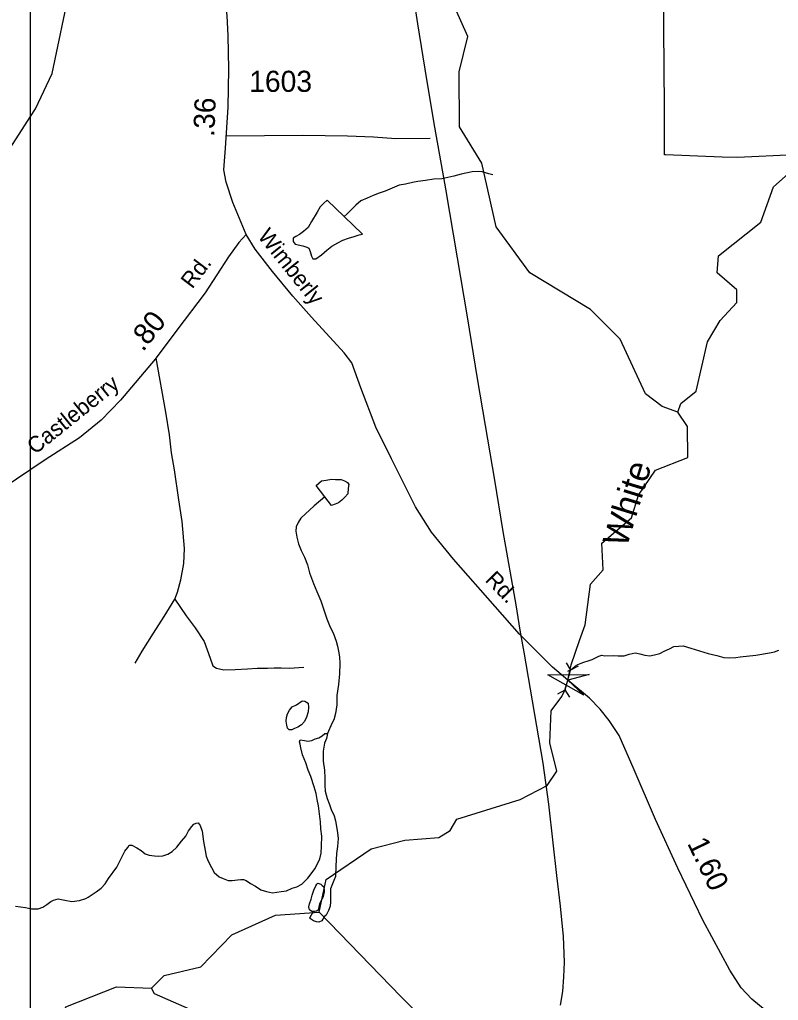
# Model space of a CAD drawing. Extents: x 2001466 to 2224147, y 644118 to 847247.
# Drawn here: x 2020409 to 2024898, y 729712 to 735517 of the extents above; entities that cross this region are included whole.
import ezdxf

# ---------------------------------------------------------------- set-up
doc = ezdxf.new("R2010")
doc.units = 0
for name, color, linetype in [('Exist Boundary Political City Limit New Hole', 7, 'Continuous'), ('Exist Hydrographic Creek Single Shore', 7, 'Continuous'), ('Exist Hydrographic Creek Single Shore Label', 7, 'Continuous'), ('Exist Hydrographic Misc Water Feature', 7, 'Continuous'), ('Exist Railroad Mainline', 7, 'Continuous'), ('Exist Road Non-System Type 51', 7, 'Continuous'), ('Exist Road Non-System Type 51 Label', 7, 'Continuous'), ('Exist Road Secondary Mileage Hundredths English Label', 7, 'Continuous'), ('Exist Road Secondary Structure Culvert CELL', 7, 'Continuous'), ('Exist Road Secondary Structure Standard Bridge Attributed CELL', 7, 'Continuous'), ('Exist Road Secondary Type 51 Attributed', 7, 'Continuous'), ('Exist Road Secondary Type 51 Label', 7, 'Continuous'), ('Exist Road Secondary Type 51 Number Label', 7, 'Continuous'), ('Map Preparation Boundary City Limit Buffer Line', 7, 'Continuous'), ('Map Preparation Inset Cut Line', 7, 'Continuous')]:
    doc.layers.add(name, color=color, linetype=linetype)

msp = doc.modelspace()

# ---------------------------------------------------------------- linework, layer by layer
at = {"layer": 'Exist Boundary Political City Limit New Hole'}
msp.add_lwpolyline([(2024992.9, 734716.5), (2024656.5, 734700.5), (2024565.2, 734702.9), (2024229.8, 734715.9), (2024225.1, 734716.1), (2024225.2, 735000), (2024214.4, 736161.1), (2024206.5, 737131.8), (2024409.8, 737216.6), (2024630.1, 737307.3), (2024732.8, 737349.6), (2024953, 736766.3)], dxfattribs=at)
at = {"layer": 'Exist Hydrographic Creek Single Shore'}
for points in [[(2024303.3, 733192.6), (2024320.3, 733244.8), (2024411.3, 733318.3), (2024478.4, 733609), (2024553.2, 733735.5), (2024653.3, 733841.7), (2024652.3, 733917.2), (2024536.4, 734018), (2024544.4, 734119.5), (2024794.4, 734317.9), (2024869.4, 734526.3), (2025377.3, 734978.6)], [(2023371.3, 730901.7), (2023530.4, 730983.8), (2023588.3, 731067.9), (2023546.4, 731236.1), (2023554.4, 731426.3), (2023616.1, 731511.5), (2023635.1, 731547.4), (2023652.7, 731608), (2023672.5, 731697.8), (2023721.3, 731842.8), (2023754.4, 731934), (2023787.4, 732176.1), (2023862.4, 732259.9), (2023854.4, 732417.6), (2024029.3, 732568.3), (2024070.3, 732701.9), (2024170.4, 732850.9), (2024362.3, 732925.7), (2024361.3, 733109.4), (2024303.3, 733192.6)], [(2022180.4, 730233.7), (2022222.4, 730426.5), (2022488.4, 730608), (2022688.3, 730659.8), (2022888.4, 730675.4), (2022955.3, 730716.6), (2022996.3, 730784.7), (2023371.3, 730901.7)], [(2021189.4, 729784.8), (2021264.4, 729858.7), (2021480.3, 729910.1), (2021664.5, 730099.9), (2021922.4, 730216), (2022180.4, 730233.7)], [(2020472.9, 729511.2), (2020531.4, 729473.4), (2020614.4, 729517.5), (2020681.4, 729673.7), (2020981.4, 729792.3), (2021189.4, 729784.8)]]:
    msp.add_lwpolyline(points, dxfattribs=at)
at = {"layer": 'Exist Hydrographic Misc Water Feature'}
for p, q in [((2022145.9, 730237.7), (2022124.2, 730198)), ((2022664.3, 729734.9), (2022180.4, 730233.7))]:
    msp.add_line(p, q, dxfattribs=at)
for points in [[(2024303.3, 733192.6), (2024211.4, 733227.3), (2024111.4, 733301.5), (2023961.3, 733626.2), (2023786.3, 733800.4), (2023428.3, 734017.7), (2023228.4, 734290.8), (2023144.3, 734666.5), (2023011.3, 734882.5), (2023010.4, 735207.3), (2023060.3, 735416.3), (2022985.4, 735585.2), (2023035.2, 735843.4), (2023060.3, 736390.8), (2023134.3, 736642), (2023109.3, 736701.5), (2022826.3, 736891.1), (2022626.4, 737118.3), (2022301.4, 737308.6), (2022042.4, 737707.6)], [(2020472.9, 734943.6), (2020502.4, 734989.5), (2020602.3, 735197.4), (2020710.4, 735716.9), (2020719.4, 735874.2), (2021060.4, 736307), (2021102.4, 736407.8), (2021368.4, 736556.6), (2021426.7, 736674)], [(2019229.5, 733365.1), (2019578.5, 733699.2), (2019703.3, 733765.6), (2019837.5, 733907.1), (2019887.3, 734040.7), (2020070.4, 734224), (2020178.5, 734280.8), (2020344.3, 734582.5), (2020352.3, 734756.3), (2020472.9, 734943.6)], [(2023207.7, 734598.8), (2023185.8, 734605), (2023165.7, 734610.3), (2023145.6, 734616.5), (2023121.6, 734618.6), (2023085.7, 734616.8), (2023021.5, 734602.6), (2022977.6, 734590.3), (2022941.7, 734582.1), (2022907.9, 734574.5), (2022859.7, 734572.3), (2022809.7, 734564.3), (2022765.8, 734558.6), (2022733.6, 734551.8), (2022691.6, 734543.7), (2022653.6, 734536.2), (2022571.8, 734501.8), (2022535.9, 734490.3), (2022500.1, 734475.4), (2022466, 734459.7), (2022427.9, 734444.1), (2022397.9, 734419.3), (2022368.2, 734389.5), (2022346.3, 734367.8), (2022329.5, 734350.9)], [(2022329.5, 734350.9), (2022228.2, 734447.3), (2022208.1, 734429.7), (2022186.1, 734409.6), (2022168.3, 734377.2), (2022136.3, 734321.2), (2022116.4, 734287.2), (2022088.1, 734263.1), (2022064.3, 734244.8), (2022042.4, 734233), (2022028.2, 734223.4), (2022026.4, 734202.9), (2022038.3, 734187.1), (2022084.4, 734178.8), (2022108.6, 734169.2), (2022120.3, 734164.9), (2022128.5, 734143.4), (2022136.5, 734117), (2022144.5, 734101.3), (2022160.5, 734100.9), (2022194.3, 734125.6), (2022226.5, 734151.3), (2022256.2, 734175.2), (2022292.5, 734195.8), (2022320.4, 734211.6), (2022354.3, 734223.3), (2022388.1, 734233.3), (2022418.2, 734243.3), (2022438.1, 734247.8), (2022329.5, 734350.9)], [(2022214.4, 732692.2), (2022162.5, 732758.9), (2022194.5, 732786.9), (2022222.4, 732790.4), (2022254.4, 732797.2), (2022278.4, 732795.1), (2022310.4, 732795.2), (2022330.5, 732786.6), (2022348.5, 732777.3), (2022356.5, 732764.7), (2022352.6, 732742.7), (2022350.8, 732709.1), (2022332.5, 732690.6), (2022314.7, 732672.9), (2022294.6, 732656.9), (2022274.9, 732649.1), (2022254.8, 732640.5), (2022214.4, 732692.2)], [(2022214.4, 732692.2), (2022151.1, 732638.6), (2022072.7, 732566.3), (2022057.1, 732540.4), (2022045, 732514.4), (2022043.2, 732488.2), (2022049.1, 732454.4), (2022059.2, 732414.8), (2022075.2, 732374.3), (2022093.4, 732336.2), (2022111.5, 732290.8), (2022123.4, 732242.1), (2022147.6, 732178.4), (2022167.7, 732132.1), (2022191.7, 732076.6), (2022211.8, 732012.3), (2022225.9, 731970.2), (2022245.8, 731920.5), (2022264, 731886.5), (2022281.9, 731838.6), (2022290.1, 731808.9), (2022296.2, 731778.4), (2022302.2, 731746.3), (2022304, 731706.1), (2022302.4, 731644.6), (2022296.4, 731582.3), (2022286.6, 731516.1), (2022286.6, 731460.4), (2022278.6, 731410.5), (2022268.8, 731372.1), (2022256.7, 731350.2), (2022230.2, 731291.7)], [(2023652.9, 731660.5), (2023669.1, 731667.6), (2023681, 731677.1), (2023696.9, 731691.6), (2023710.7, 731699.5), (2023730.8, 731707.3), (2023746.8, 731713.5), (2023772.8, 731721.2), (2023797, 731729.7), (2023820.8, 731741.5), (2023836.8, 731750.2), (2023852.8, 731755.7), (2023870.8, 731752), (2023922.7, 731752.6), (2023950.8, 731750.4), (2023986.7, 731750.5), (2024014.8, 731760.6), (2024050.7, 731768.9), (2024078.8, 731762.6), (2024108.7, 731755.4), (2024136.8, 731751.5), (2024164.7, 731757.5), (2024196.7, 731765.1), (2024222.5, 731779.3), (2024254.5, 731793.4), (2024280.5, 731806), (2024334.7, 731809.8), (2024380.8, 731796.5), (2024482.7, 731764.9), (2024534.8, 731753.2), (2024574.8, 731740.9), (2024608.8, 731739.4), (2024646.7, 731741.1), (2024672.8, 731745.5), (2024764.7, 731755.9), (2024844.8, 731769.9), (2024874.8, 731774.2), (2024900.8, 731784.3)], [(2021988.9, 731340.1), (2021986.8, 731363.9), (2021988.7, 731386), (2021992.8, 731408.1), (2022004.7, 731430), (2022020.6, 731450.2), (2022046.5, 731461.9), (2022080.5, 731484.2), (2022096.5, 731483.9), (2022116.6, 731470.4), (2022118.7, 731448.2), (2022116.8, 731420.3), (2022106.8, 731387.7), (2022094.7, 731361.7), (2022076.8, 731342.4), (2022054.9, 731328.1), (2022034.8, 731320.3), (2022018.8, 731314), (2022002.8, 731313.5), (2021994.6, 731323.6), (2021988.9, 731340.1)], [(2022064.9, 731241.7), (2022069, 731254), (2022094.9, 731250.1), (2022115, 731246.4), (2022136.9, 731250.1), (2022157, 731260.3), (2022178.9, 731266.5), (2022198.8, 731278.4), (2022214.8, 731292), (2022230.2, 731291.7)], [(2022230.2, 731291.7), (2022225.1, 731262.3), (2022212.8, 731233.8), (2022205, 731186.4), (2022205.2, 731128.1), (2022213.4, 731073.8), (2022215.2, 731027.9), (2022215.4, 730986), (2022217.3, 730949.9), (2022227.5, 730907.8), (2022241.3, 730872.3), (2022251.5, 730841.7), (2022269.6, 730804.4), (2022277.6, 730773.9), (2022283.9, 730740.2), (2022290.1, 730704), (2022293.8, 730670.3), (2022289.9, 730622), (2022284.1, 730581.8), (2022282.1, 730544.1), (2022280, 730505.6), (2022277.2, 730445)], [(2020384.7, 730269.6), (2020442.8, 730261.8), (2020478.7, 730253.7), (2020518.8, 730253.7), (2020546.7, 730263.7), (2020570.7, 730279.7), (2020592.7, 730297.3), (2020608.7, 730306), (2020636.5, 730312), (2020676.5, 730305.5), (2020718.6, 730298), (2020762.4, 730303.7), (2020800.8, 730314.4), (2020814.5, 730322.3), (2020862.3, 730354.2), (2020890.4, 730376.5), (2020914.4, 730402.2), (2020934.3, 730433.9), (2020984.3, 730500.1), (2021002.2, 730536.6), (2021014.2, 730560.2), (2021032.1, 730594.3), (2021048.3, 730616.1), (2021056.1, 730630.7), (2021072.1, 730630.4), (2021102.2, 730614.2), (2021128.1, 730598.9), (2021152, 730578.7), (2021176, 730570.8), (2021206.2, 730566.9), (2021232.2, 730566.4), (2021256.2, 730568.4), (2021286.1, 730576.8), (2021312, 730592.7), (2021338, 730619.2), (2021365.9, 730654.8), (2021392.2, 730684.6), (2021407.9, 730714.6), (2021427.8, 730741.2), (2021439.9, 730754.9), (2021453.9, 730761.2), (2021465.8, 730762.6), (2021477.9, 730746.8), (2021487.9, 730712.9), (2021495.9, 730652.9), (2021506.2, 730599.4), (2021511.9, 730564.8), (2021524.2, 730535), (2021544.3, 730499.3), (2021560.3, 730468.6), (2021590, 730443.5), (2021614, 730433.1), (2021642.5, 730421.1), (2021666.3, 730421.4), (2021698.3, 730424.8), (2021718.2, 730426.9), (2021734.2, 730427.4), (2021748.3, 730421.3), (2021774.4, 730403.6), (2021804.3, 730387.4), (2021836.3, 730365.4), (2021870.3, 730355.7), (2021904.6, 730349.3), (2021956.3, 730355.6), (2021988.5, 730359.8), (2022020.4, 730375.6), (2022048.3, 730383.3), (2022078.1, 730399.8), (2022114.1, 730436), (2022158, 730491.8), (2022184.1, 730550.3), (2022192.1, 730583.8), (2022195.8, 730625.5), (2022197.8, 730683.7), (2022191.7, 730728.2), (2022189.6, 730768.4), (2022183.7, 730816), (2022177.5, 730863.8), (2022169.5, 730900), (2022163.6, 730936.2), (2022151.5, 730975.8), (2022131.2, 731036.2), (2022115.4, 731074.2), (2022103.1, 731117.9), (2022083.2, 731165.9), (2022073.1, 731206.2), (2022069, 731227.7), (2022064.9, 731241.7)], [(2022277.2, 730445), (2022268.1, 730422.2), (2022256.2, 730392.1), (2022248.5, 730371.8), (2022248.3, 730345.5), (2022248.5, 730316), (2022248.3, 730295.5), (2022246.4, 730270.1), (2022236.6, 730244.1), (2022223.4, 730216.5)], [(2022145.9, 730237.7), (2022138.5, 730237.8), (2022124.4, 730247.9), (2022120.5, 730265.3), (2022124.4, 730284.1), (2022134.4, 730311.8), (2022140.4, 730335.4), (2022150.4, 730363.9), (2022162.3, 730390), (2022166.4, 730399.7), (2022174.2, 730406.1), (2022190.4, 730400), (2022198, 730391.6), (2022206.2, 730385.8), (2022210.5, 730370.1), (2022210.3, 730353.7), (2022204.6, 730327.6), (2022198.4, 730313.7), (2022184.7, 730287.8), (2022180.6, 730273.9), (2022176.5, 730256), (2022174.4, 730245.3), (2022164.4, 730239.8), (2022152.7, 730237.6), (2022145.9, 730237.7)], [(2022223.4, 730216.5), (2022210.5, 730206), (2022196.6, 730183.3), (2022178.5, 730175.5), (2022164.6, 730177.4), (2022146.8, 730181.9), (2022124.2, 730198)], [(2021814.4, 729276.5), (2021606.4, 729576.1), (2021206.4, 729751.6), (2021189.4, 729784.8)], [(2024211, 727966.9), (2024106.4, 728110.9), (2023856.3, 728368.7), (2023264.3, 728777.8), (2023148.4, 728901.6), (2022997.3, 729344.3), (2022906.3, 729493.8), (2022664.3, 729734.9)]]:
    msp.add_lwpolyline(points, dxfattribs=at)
at = {"layer": 'Exist Railroad Mainline'}
for points in [[(2022606.9, 736481.3), (2022607.1, 736480), (2022632.7, 736331.9), (2022672.1, 736069.9), (2022713.4, 735818), (2022762.5, 735492), (2022815.8, 735161.8), (2022863, 734879.8), (2022928.2, 734515.9), (2022997.1, 734107.8), (2023056.1, 733757.8), (2023115.2, 733391.8), (2023162.6, 733113.6), (2023217.8, 732791.6), (2023267, 732487.6), (2023343.9, 732053.6), (2023369.3, 731903.2)], [(2023369.3, 731903.2), (2023391.2, 731773.6), (2023503.6, 731115.4), (2023538.8, 730873.5), (2023564.3, 730643.5), (2023585.8, 730451.5), (2023607.3, 730269.4), (2023624.8, 730089.4), (2023630.5, 729937.5), (2023626.3, 729851.6), (2023620.1, 729763.7), (2023607.9, 729683.7)]]:
    msp.add_lwpolyline(points, dxfattribs=at)
at = {"layer": 'Exist Road Non-System Type 51'}
for points in [[(2021631.6, 734829.2), (2022085.1, 734833.6), (2022348.7, 734828.8), (2022502.8, 734822.2), (2022635.7, 734813.2), (2022837.8, 734814.4)], [(2021326.6, 732086.7), (2021342.4, 732128.8), (2021362.6, 732200.7), (2021379.5, 732297.9), (2021383.7, 732386.7), (2021371.1, 732547.3), (2021349.9, 732674.2), (2021324.6, 732851.7), (2021307.7, 732953.2), (2021295, 733058.9), (2021273.9, 733194.1), (2021216, 733512.7)], [(2021093.3, 731707.2), (2021133.6, 731779.1), (2021200.3, 731886.2), (2021263.4, 731984.5), (2021326.6, 732086.7)], [(2021326.6, 732086.7), (2021395, 731988.4), (2021447.6, 731916.4), (2021500.3, 731835.7), (2021537.1, 731737.4), (2021552.4, 731692.3), (2021574.3, 731678.3), (2021616.3, 731668), (2021683.4, 731670.3), (2021757.1, 731673.8), (2021815, 731679.1), (2021876.4, 731679.1), (2021915, 731680.8), (2021955.3, 731680.8), (2022004.5, 731679.1), (2022090.4, 731684.3)]]:
    msp.add_lwpolyline(points, dxfattribs=at)
at = {"layer": 'Exist Road Secondary Structure Culvert CELL'}
for p, q in [((2023641.9, 731709.7), (2023668.4, 731666.4)), ((2023637, 731549.6), (2023668.4, 731666.4)), ((2023713.1, 731690.5), (2023668.4, 731666.4)), ((2023592.3, 731525.5), (2023637, 731549.6)), ((2023663.5, 731506.3), (2023637, 731549.6))]:
    msp.add_line(p, q, dxfattribs=at)
at = {"layer": 'Exist Road Secondary Structure Standard Bridge Attributed CELL'}
msp.add_lwpolyline([(2023746.7, 731518.2), (2023534.7, 731638.8), (2023778.6, 731640.4), (2023652.7, 731608)], close=True, dxfattribs=at)
at = {"layer": 'Exist Road Secondary Type 51 Attributed'}
for points in [[(2021749.9, 734244.5), (2021671.1, 734435.3), (2021630.8, 734554.5), (2021618, 734628.6), (2021626.8, 734755), (2021642.5, 734998.1), (2021647.3, 735223.5), (2021643.3, 735423.2), (2021637.3, 735539.1), (2021603.5, 735812.9), (2021590.6, 736012.5), (2021587, 736147.8)], [(2021749.9, 734244.5), (2021704.9, 734197), (2021645.3, 734113.3), (2021506.1, 733899.9), (2021338.8, 733679.3), (2021210.5, 733506.2), (2021005.3, 733264.7), (2020891.1, 733145.6), (2020763.6, 733042.5), (2020560.8, 732911.3), (2020134.4, 732624.7), (2019756.7, 732379.9), (2019446.9, 732188.3), (2019358.4, 732156.1), (2019202.4, 732114.2), (2018963, 732057.1), (2018704.7, 731991.8), (2018354, 731909.7)], [(2023652.7, 731608), (2023561.8, 731685), (2023366.1, 731878.6), (2023222.5, 732043.9), (2022975.2, 732323.5), (2022844.9, 732483), (2022752, 732633.5), (2022608.8, 732916.9), (2022516.6, 733104.5), (2022428.1, 733338), (2022375, 733484.5), (2022328.4, 733544.1), (2022134.9, 733756.6), (2022025.5, 733880.6), (2021904.8, 734025.5), (2021801.8, 734158.4), (2021749.9, 734244.5)], [(2024820.8, 729653.8), (2024740.4, 729719.8), (2024677.6, 729785.8), (2024611.7, 729890.5), (2024450.8, 730186), (2024303.9, 730494.3), (2024170.8, 730783.4), (2024045.3, 731076.4), (2023956.4, 731279.3), (2023896.8, 731368.2), (2023844.7, 731434.9), (2023781, 731500.9), (2023652.7, 731608)]]:
    msp.add_lwpolyline(points, dxfattribs=at)
at = {"layer": 'Map Preparation Boundary City Limit Buffer Line'}
msp.add_lwpolyline([(2024992.9, 734716.5), (2024656.5, 734700.5), (2024565.2, 734702.9), (2024229.8, 734715.9), (2024225.1, 734716.1), (2024225.2, 735000), (2024214.4, 736161.1), (2024206.5, 737131.8), (2024409.8, 737216.6), (2024630.1, 737307.3), (2024732.8, 737349.6), (2024953, 736766.3)], dxfattribs=at)
at = {"layer": 'Map Preparation Inset Cut Line'}
for p, q in [((2020472.9, 734943.6), (2020472.9, 735780)), ((2020472.9, 732875.9), (2020472.9, 734943.6)), ((2020472.9, 729511.2), (2020472.9, 732875.9))]:
    msp.add_line(p, q, dxfattribs=at)

# ---------------------------------------------------------------- texts
at = {"layer": 'Exist Hydrographic Creek Single Shore Label'}
msp.add_text('White', height=150, rotation=72.94038, dxfattribs=at).set_placement((2023999.5, 732386.2))
at = {"layer": 'Exist Road Non-System Type 51 Label'}
for s, rotation, p in [('Rd.', 52.86328, (2021430.3, 733918.9)), ('Castleberry', 38.74513, (2020499.9, 732939.2))]:
    msp.add_text(s, height=95, rotation=rotation, dxfattribs=at).set_placement(p)
at = {"layer": 'Exist Road Secondary Mileage Hundredths English Label'}
for s, rotation, p in [('.36', 87.76824, (2021560.6, 734821.4)), ('.80', 51.91291, (2021138.7, 733546.6)), ('1.60', 295.70951, (2024357, 730641.4))]:
    msp.add_text(s, height=125, rotation=rotation, dxfattribs=at).set_placement(p)
at = {"layer": 'Exist Road Secondary Type 51 Label'}
for s, rotation, p in [('Wimberly', 308.66804, (2021813.2, 734233.2)), ('Rd.', 314.30129, (2023158.2, 732196.4))]:
    msp.add_text(s, height=95, rotation=rotation, dxfattribs=at).set_placement(p)
at = {"layer": 'Exist Road Secondary Type 51 Number Label'}
msp.add_text('1603', height=125, dxfattribs=at).set_placement((2021767.2, 735089.2))

doc.saveas('drawing.dxf')
